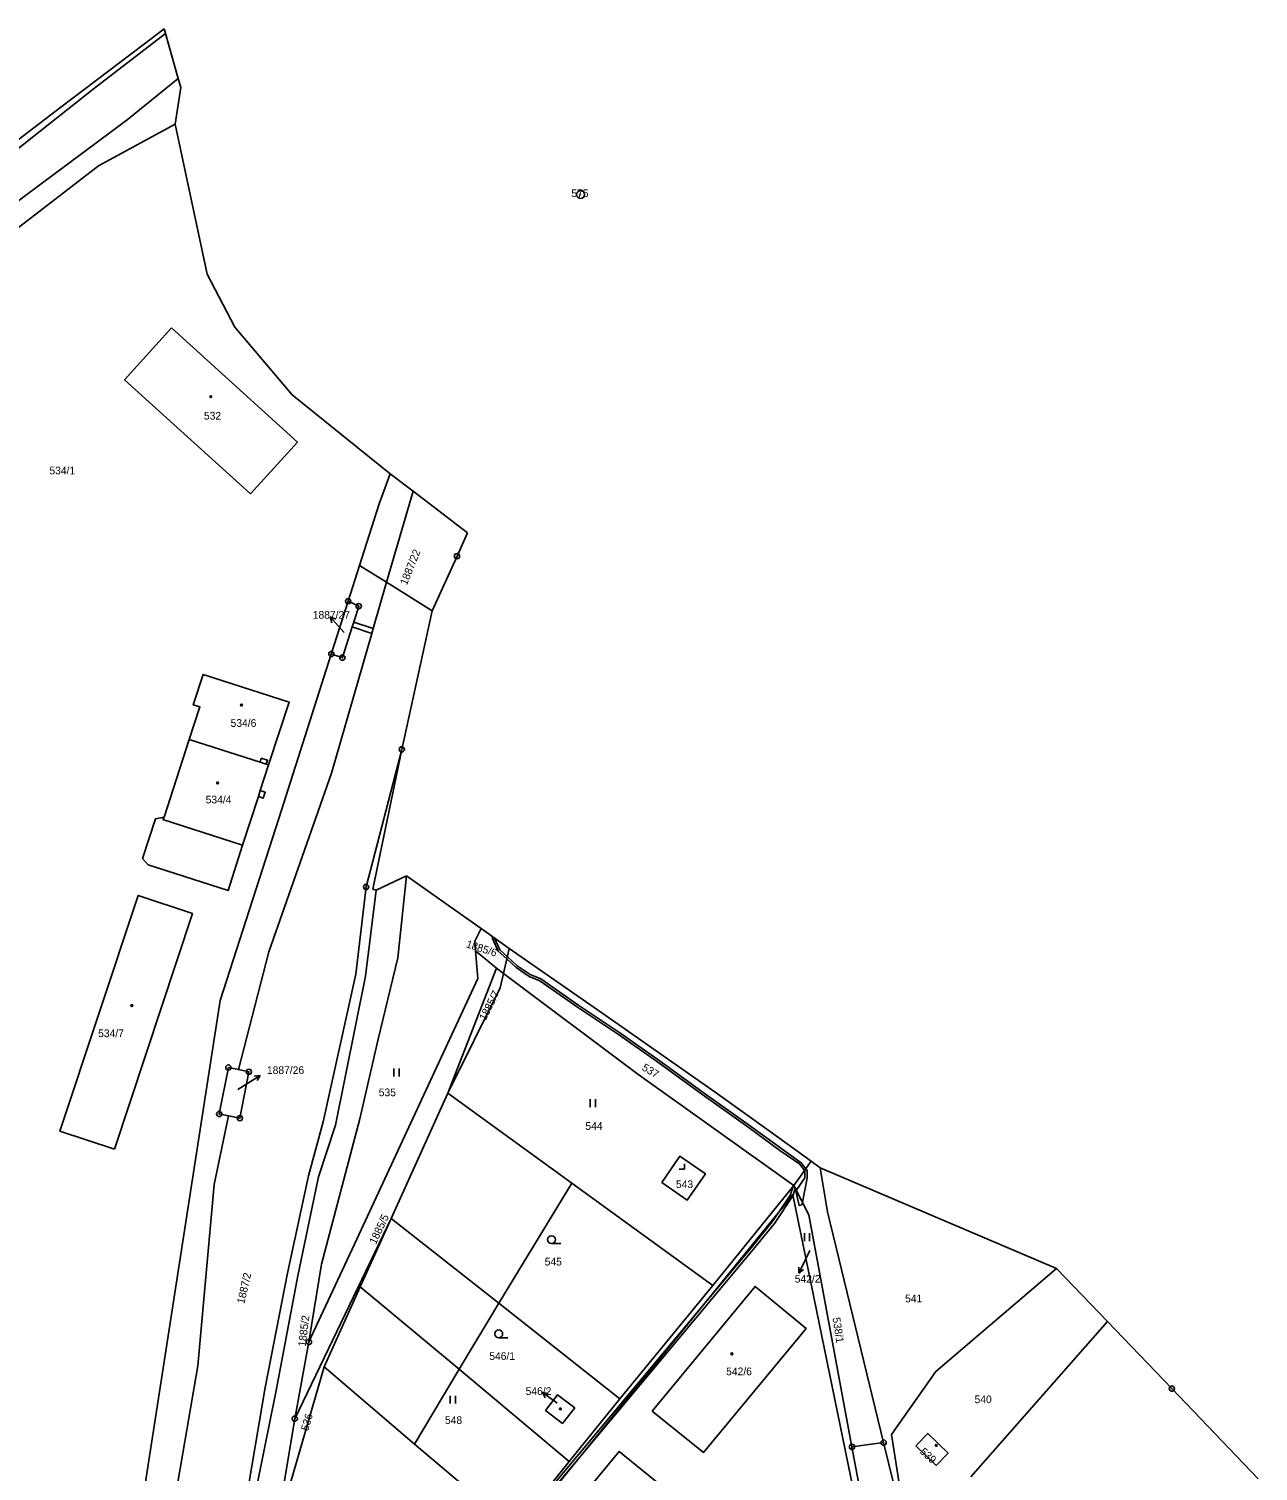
# Model space of a CAD drawing. Extents: x -587171 to -555306, y -1167727 to -1074732.
# Drawn here: x -561111.1 to -560877.8, y -1077658.3 to -1077384.6 of the extents above; entities that cross this region are included whole.
import ezdxf

# ---------------------------------------------------------------- set-up
doc = ezdxf.new("R2010")
doc.units = 0
for name, color, linetype in [('Hranice parcel', 7, 'Continuous'), ('Parcelní čísla', 7, 'Continuous'), ('Pop  PČ popisy', 7, 'Continuous'), ('Vnitřní kresba', 7, 'Continuous'), ('Věcná břemena k části', 7, 'Continuous'), ('Značky bodu BP', 7, 'Continuous'), ('Značky budov', 7, 'Continuous'), ('Značky kultur', 7, 'Continuous')]:
    doc.layers.add(name, color=color, linetype=linetype)

msp = doc.modelspace()

# ---------------------------------------------------------------- linework, layer by layer
at = {"layer": 'Hranice parcel'}
for p, q in [((-561089.39, -1077387.63), (-561085.41, -1077384.6)), ((-561104.98, -1077399.49), (-561089.39, -1077387.63)), ((-561083.3, -1077402.66), (-561082.24, -1077395.75)), ((-561136.14, -1077423.19), (-561104.98, -1077399.49)), ((-561097.85, -1077410.62), (-561083.3, -1077402.66)), ((-561077.2, -1077431.15), (-561083.3, -1077402.66)), ((-561044.6, -1077474.75), (-561042.48, -1077469.05)), ((-561048.31, -1077486.41), (-561044.6, -1077474.75)), ((-561038.17, -1077472.34), (-561027.8, -1077480.27)), ((-561027.8, -1077480.27), (-561029.82, -1077484.67)), ((-561029.82, -1077484.67), (-561034.56, -1077495.01)), ((-561050.47, -1077493.22), (-561048.31, -1077486.41)), ((-561050.47, -1077493.22), (-561053.67, -1077503.25)), ((-561034.56, -1077495.01), (-561040.3, -1077521.34)), ((-561040.3, -1077521.34), (-561047.07, -1077547.44)), ((-561040.3, -1077521.34), (-561045.79, -1077547.85)), ((-561045.15, -1077548.03), (-561039.41, -1077545.32)), ((-561039.41, -1077545.32), (-561041.08, -1077560.86)), ((-561035.74, -1077547.92), (-561039.41, -1077545.32)), ((-561045.15, -1077548.03), (-561047.16, -1077564.4)), ((-561045.79, -1077547.85), (-561045.15, -1077548.03)), ((-561028.18, -1077553.26), (-561035.74, -1077547.92)), ((-561025.24, -1077555.34), (-561028.18, -1077553.26)), ((-561026.45, -1077557.71), (-561025.24, -1077555.34)), ((-561025.24, -1077555.34), (-561019.93, -1077559.09)), ((-561026.3, -1077559.58), (-561026.45, -1077557.71)), ((-561022.35, -1077562.87), (-561026.3, -1077559.58)), ((-561019.93, -1077559.09), (-561021.01, -1077563.88)), ((-561019.93, -1077559.09), (-561002.33, -1077571.3)), ((-561031.57, -1077586.54), (-561022.35, -1077562.87)), ((-561022.35, -1077562.87), (-561021.01, -1077563.88)), ((-561021.01, -1077563.88), (-561021.61, -1077566.57)), ((-561021.01, -1077563.88), (-560995.54, -1077582.99)), ((-561021.61, -1077566.57), (-561031.57, -1077586.54)), ((-561002.33, -1077571.3), (-560980.81, -1077586.39)), ((-560995.54, -1077582.99), (-560965.94, -1077604.07)), ((-561031.57, -1077586.54), (-561042.32, -1077610.36)), ((-560980.81, -1077586.39), (-560971.06, -1077593.43)), ((-560971.06, -1077593.43), (-560962.64, -1077599.49)), ((-560965.94, -1077604.07), (-560962.64, -1077599.49)), ((-560962.64, -1077599.49), (-560960.9, -1077600.75)), ((-560960.9, -1077600.75), (-560916.1, -1077619.85)), ((-560981.28, -1077623.05), (-560965.94, -1077604.07)), ((-561042.32, -1077610.36), (-561060.6, -1077648.34)), ((-561048.19, -1077623.34), (-561042.32, -1077610.36)), ((-560916.1, -1077619.85), (-560906.37, -1077629.88)), ((-561055, -1077638.52), (-561048.19, -1077623.34)), ((-560998.9, -1077644.59), (-560981.28, -1077623.05)), ((-560932.31, -1077659.38), (-560906.37, -1077629.88)), ((-560906.37, -1077629.88), (-560894.18, -1077642.64)), ((-561060.6, -1077648.34), (-561057.92, -1077633.79)), ((-561064.14, -1077669.78), (-561055, -1077638.52)), ((-561066.21, -1077642.45), (-561069.95, -1077664.47)), ((-560894.18, -1077642.64), (-560877.81, -1077659.77)), ((-561008.51, -1077656.44), (-560998.9, -1077644.59)), ((-560954.88, -1077653.68), (-560948.87, -1077652.87)), ((-560954.88, -1077653.68), (-560951.31, -1077672.99)), ((-560944.05, -1077672.73), (-560948.87, -1077652.87)), ((-561018.85, -1077669.25), (-561008.51, -1077656.44))]:
    msp.add_line(p, q, dxfattribs=at)
for points in [[(-561082.24, -1077395.75), (-561082.73, -1077394.02), (-561085.16, -1077385.46), (-561085.41, -1077384.6)], [(-561186.29, -1077567.08), (-561184.34, -1077548.64), (-561179.96, -1077521.59), (-561171.23, -1077492.79), (-561162.55, -1077475.12), (-561152.1, -1077458.73), (-561141.46, -1077444.02), (-561123.47, -1077428.97), (-561118.92, -1077426.82), (-561097.85, -1077410.62)], [(-561042.48, -1077469.05), (-561061.08, -1077454.04), (-561071.96, -1077441.19), (-561077.2, -1077431.15)], [(-561084.02, -1077441.36), (-561060.11, -1077463.02), (-561069, -1077472.82), (-561092.91, -1077451.18), (-561084.02, -1077441.36)], [(-561042.48, -1077469.05), (-561038.9, -1077471.78), (-561038.17, -1077472.34)], [(-561034.56, -1077495.01), (-561043.17, -1077489.63), (-561048.31, -1077486.41)], [(-561053.67, -1077503.25), (-561051.57, -1077503.92), (-561049.72, -1077498.1), (-561049.43, -1077497.19), (-561048.47, -1077494.15), (-561050.47, -1077493.22)], [(-561091.86, -1077681.63), (-561089.7, -1077665.29), (-561074.75, -1077568.98), (-561063.6, -1077534.48), (-561053.67, -1077503.25)], [(-561065.57, -1077524.27), (-561063.56, -1077518.16), (-561061.68, -1077512.35), (-561078, -1077507.1), (-561079.88, -1077512.86), (-561078.6, -1077513.27), (-561080.62, -1077519.46)], [(-561080.62, -1077519.46), (-561085.39, -1077534.21), (-561087.06, -1077534.53), (-561089.47, -1077542.01), (-561088.41, -1077543.24), (-561073.26, -1077548.12), (-561070.5, -1077539.52)], [(-561065.57, -1077524.27), (-561066.01, -1077524.13), (-561065.77, -1077523.41), (-561066.97, -1077523.03), (-561067.2, -1077523.73), (-561080.62, -1077519.46)], [(-561070.5, -1077539.52), (-561067.51, -1077530.27), (-561066.6, -1077530.56), (-561066.25, -1077529.44), (-561067.15, -1077529.15), (-561065.57, -1077524.27)], [(-561047.07, -1077547.44), (-561049.05, -1077564.01), (-561055.23, -1077591.99), (-561058.03, -1077602.23), (-561061.99, -1077620.72), (-561066.21, -1077642.45)], [(-561094.83, -1077597.2), (-561080.04, -1077552.47), (-561090.35, -1077549.03), (-561105.17, -1077593.77), (-561094.83, -1077597.2)], [(-561057.92, -1077633.79), (-561048.86, -1077614.29), (-561025.87, -1077564.82), (-561026.3, -1077559.58)], [(-561041.08, -1077560.86), (-561044.81, -1077576.33), (-561048.24, -1077591.47), (-561055.56, -1077618.99), (-561057.92, -1077633.79)], [(-561047.16, -1077564.4), (-561052.89, -1077592.64), (-561056.11, -1077602.43), (-561060, -1077621.24), (-561064.23, -1077643.29), (-561067.46, -1077659.56), (-561068.21, -1077663.34)], [(-561069.31, -1077582.52), (-561071.29, -1077582.11), (-561073.21, -1077581.71), (-561074.93, -1077590.51), (-561073.21, -1077590.87), (-561071.02, -1077591.32), (-561069.31, -1077582.52)], [(-561031.57, -1077586.54), (-561008.03, -1077603.66), (-560981.28, -1077623.05)], [(-560990.97, -1077603.55), (-560986.18, -1077606.89), (-560982.7, -1077601.89), (-560987.52, -1077598.53), (-560990.97, -1077603.55)], [(-560948.87, -1077652.87), (-560959.51, -1077609.08), (-560960.9, -1077600.75)], [(-560952.12, -1077674.01), (-560966.12, -1077605.89), (-561018.09, -1077669.9)], [(-560965.94, -1077604.07), (-560963.04, -1077609.64), (-560954.88, -1077653.68)], [(-561042.32, -1077610.36), (-561021.9, -1077626.43), (-560998.9, -1077644.59)], [(-560916.1, -1077619.85), (-560938.99, -1077639.39), (-560947.41, -1077651.33), (-560944.05, -1077672.73)], [(-561048.19, -1077623.34), (-561029.43, -1077638.93), (-561008.51, -1077656.44)], [(-560992.78, -1077646.93), (-560973.25, -1077623.25), (-560963.58, -1077631.23), (-560983.08, -1077654.78), (-560992.78, -1077646.93)], [(-561055, -1077638.52), (-561037.9, -1077653.16), (-561018.85, -1077669.25)], [(-561013.05, -1077646.78), (-561010.74, -1077643.79), (-561007.47, -1077646.31), (-561009.82, -1077649.25), (-561013.05, -1077646.78)], [(-561060.6, -1077648.34), (-561062.29, -1077658.56), (-561064.14, -1077669.78)], [(-560942.77, -1077653.5), (-560938.9, -1077657.22), (-560936.64, -1077654.88), (-560940.5, -1077651.13), (-560942.77, -1077653.5)], [(-561014.38, -1077673.09), (-560999.06, -1077654.59), (-560984.66, -1077666.25), (-561000.35, -1077685.17)]]:
    msp.add_lwpolyline(points, dxfattribs=at)
at = {"layer": 'Pop  PČ popisy'}
for p, q in [((-561051.86, -1077498.44), (-561053.87, -1077496.21)), ((-561053.87, -1077496.21), (-561052.83, -1077496.62)), ((-561053.87, -1077496.21), (-561053.57, -1077497.29)), ((-561051.22, -1077499.14), (-561051.86, -1077498.44)), ((-561069.73, -1077584.82), (-561067.19, -1077583.23)), ((-561067.19, -1077583.23), (-561068.3, -1077583.34)), ((-561067.19, -1077583.23), (-561067.77, -1077584.19)), ((-561071.4, -1077585.88), (-561069.73, -1077584.82)), ((-560962.88, -1077616.45), (-560963.64, -1077618.01)), ((-560964.96, -1077620.71), (-560964.97, -1077619.59)), ((-560963.64, -1077618.01), (-560964.96, -1077620.71)), ((-560964.96, -1077620.71), (-560964.07, -1077620.03)), ((-561011.15, -1077645.12), (-561013.61, -1077643.4)), ((-561013.61, -1077643.4), (-561012.5, -1077643.56)), ((-561013.61, -1077643.4), (-561013.08, -1077644.38)), ((-561010.8, -1077645.37), (-561011.15, -1077645.12))]:
    msp.add_line(p, q, dxfattribs=at)
at = {"layer": 'Vnitřní kresba'}
for p, q in [((-561098.89, -1077396.06), (-561085.16, -1077385.46)), ((-561092.38, -1077401.88), (-561082.73, -1077394.02)), ((-561122.69, -1077414.91), (-561098.89, -1077396.06)), ((-561117.31, -1077420.35), (-561092.38, -1077401.88)), ((-561043.17, -1077489.63), (-561038.17, -1077472.34)), ((-561045.7, -1077498.4), (-561043.17, -1077489.63)), ((-561053.63, -1077525.84), (-561045.98, -1077499.36)), ((-561045.98, -1077499.36), (-561049.72, -1077498.1)), ((-561049.43, -1077497.19), (-561045.7, -1077498.4)), ((-561045.98, -1077499.36), (-561045.7, -1077498.4)), ((-561066.01, -1077524.13), (-561067.2, -1077523.73)), ((-561065.55, -1077559.77), (-561053.63, -1077525.84)), ((-561067.51, -1077530.27), (-561067.15, -1077529.15)), ((-561085.39, -1077534.21), (-561085.61, -1077534.64)), ((-561085.61, -1077534.64), (-561070.5, -1077539.52)), ((-561071.29, -1077582.11), (-561065.55, -1077559.77)), ((-561075.89, -1077603.92), (-561073.21, -1077590.87)), ((-561079.03, -1077638.29), (-561075.89, -1077603.92)), ((-561021.9, -1077626.43), (-561008.03, -1077603.66)), ((-561029.43, -1077638.93), (-561021.9, -1077626.43)), ((-561037.9, -1077653.16), (-561029.43, -1077638.93))]:
    msp.add_line(p, q, dxfattribs=at)
msp.add_lwpolyline([(-561092.24, -1077729.79), (-561088.54, -1077699.33), (-561083.87, -1077666.65), (-561079.03, -1077638.29)], dxfattribs=at)
at = {"layer": 'Věcná břemena k části'}
for points in [[(-561022.69, -1077557.14), (-561023.06, -1077556.88), (-561023.11, -1077557.21), (-561022.02, -1077559.6), (-561020.38, -1077561.1), (-561018.62, -1077562.72), (-561016.13, -1077564.41), (-561014.1, -1077565.24), (-561006.93, -1077570.24), (-560999.17, -1077575.46), (-560991.95, -1077580.51), (-560983.36, -1077586.75), (-560974.36, -1077593.15), (-560968.56, -1077597.42), (-560964.78, -1077600.06), (-560963.91, -1077601.25), (-560963.8, -1077601.4), (-560963.81, -1077602.62), (-560965.44, -1077605.03), (-560964.29, -1077607.23), (-560963.41, -1077602.72), (-560963.4, -1077601.26), (-560963.66, -1077600.91), (-560964.5, -1077599.77), (-560974.12, -1077592.83), (-560983.12, -1077586.43), (-560991.71, -1077580.19), (-560998.95, -1077575.13), (-561006.71, -1077569.91), (-561013.9, -1077564.88), (-561015.94, -1077564.05), (-561018.38, -1077562.4), (-561020.28, -1077560.65), (-561021.69, -1077559.36)], [(-560964.29, -1077607.23), (-560965.44, -1077605.03), (-560965.52, -1077605.14), (-560964.89, -1077607.89), (-560964.4, -1077607.78)]]:
    msp.add_lwpolyline(points, close=True, dxfattribs=at)
msp.add_lwpolyline([(-561012.37, -1077662.64), (-561005.97, -1077654.97), (-560973.63, -1077616.21), (-560969.6, -1077611.29), (-560966.09, -1077606.05), (-560965.67, -1077604.65), (-560965.65, -1077604.63), (-560965.88, -1077604.18), (-560966.11, -1077604.35), (-560966.55, -1077605.84), (-560968.77, -1077609.15), (-560970, -1077610.99), (-560974.01, -1077615.89), (-560982.44, -1077625.99), (-561012.75, -1077662.32)], dxfattribs=at)
at = {"layer": 'Značky bodu BP'}
for centre, radius in [((-561006.37, -1077416.03), 0.75), ((-561006.37, -1077416.03), 0.03), ((-561029.82, -1077484.67), 0.5), ((-561029.82, -1077484.67), 0.0303), ((-561050.47, -1077493.22), 0.5), ((-561050.47, -1077493.22), 0.0303), ((-561048.47, -1077494.15), 0.5), ((-561048.47, -1077494.15), 0.0303), ((-561053.67, -1077503.25), 0.5), ((-561053.67, -1077503.25), 0.0303), ((-561051.57, -1077503.92), 0.5), ((-561051.57, -1077503.92), 0.0303), ((-561040.3, -1077521.34), 0.5), ((-561040.3, -1077521.34), 0.0303), ((-561047.07, -1077547.44), 0.5), ((-561047.07, -1077547.44), 0.0303), ((-561073.21, -1077581.71), 0.5), ((-561073.21, -1077581.71), 0.0303), ((-561069.31, -1077582.52), 0.5), ((-561069.31, -1077582.52), 0.0303), ((-561074.93, -1077590.51), 0.5), ((-561074.93, -1077590.51), 0.0303), ((-561071.02, -1077591.32), 0.5), ((-561071.02, -1077591.32), 0.0303), ((-561057.92, -1077633.79), 0.5), ((-561057.92, -1077633.79), 0.0303), ((-560894.18, -1077642.64), 0.5), ((-560894.18, -1077642.64), 0.0303), ((-561060.6, -1077648.34), 0.5), ((-561060.6, -1077648.34), 0.0303), ((-560948.87, -1077652.87), 0.5), ((-560954.88, -1077653.68), 0.5), ((-560954.88, -1077653.68), 0.0303), ((-560948.87, -1077652.87), 0.0303)]:
    msp.add_circle(centre, radius, dxfattribs=at)
at = {"layer": 'Značky budov'}
for centre in [(-561076.53, -1077454.4), (-561070.72, -1077512.92), (-561075.24, -1077527.7), (-561091.51, -1077569.94), (-560977.66, -1077636.03), (-561010.21, -1077646.5), (-560938.88, -1077653.41)]:
    msp.add_circle(centre, 0.175, dxfattribs=at)
at = {"layer": 'Značky kultur'}
for p, q in [((-561041.79, -1077583.42), (-561041.79, -1077581.92)), ((-561040.79, -1077583.42), (-561040.79, -1077581.92)), ((-561004.54, -1077589.24), (-561004.54, -1077587.74)), ((-561003.54, -1077589.24), (-561003.54, -1077587.74)), ((-560986.67, -1077600.99), (-560986.67, -1077599.99)), ((-560987.67, -1077600.99), (-560986.67, -1077600.99)), ((-560963.91, -1077614.64), (-560963.91, -1077613.14)), ((-560962.91, -1077614.64), (-560962.91, -1077613.14)), ((-561011.89, -1077615.12), (-561010.14, -1077615.12)), ((-561021.91, -1077632.99), (-561020.16, -1077632.99)), ((-561031.14, -1077645.48), (-561031.14, -1077643.98)), ((-561030.14, -1077645.48), (-561030.14, -1077643.98))]:
    msp.add_line(p, q, dxfattribs=at)
for centre in [(-561011.89, -1077614.37), (-561021.91, -1077632.24)]:
    msp.add_circle(centre, 0.75, dxfattribs=at)

# ---------------------------------------------------------------- texts
at = {"layer": 'Parcelní čísla'}
for s, p in [('532', (-561077.84, -1077458.75)), ('534/1', (-561107.16, -1077469.14)), ('1887/27', (-561057.19, -1077496.53)), ('534/6', (-561072.78, -1077517.06)), ('534/4', (-561077.51, -1077531.59)), ('534/7', (-561097.92, -1077575.94)), ('1887/26', (-561065.89, -1077582.93)), ('535', (-561044.67, -1077587.15)), ('544', (-561005.46, -1077593.53)), ('543', (-560988.28, -1077604.58)), ('545', (-561013.18, -1077619.27)), ('542/2', (-560965.74, -1077622.52)), ('541', (-560944.81, -1077626.26)), ('546/1', (-561023.7, -1077637.2)), ('542/6', (-560978.75, -1077640.1)), ('546/2', (-561016.8, -1077643.84)), ('540', (-560931.62, -1077645.4)), ('548', (-561032.11, -1077649.35))]:
    msp.add_text(s, height=1.46, dxfattribs=at).set_placement(p)
for s, rotation, p in [('1887/22', 68, (-561039.35, -1077490.28)), ('1885/6', 342, (-561028.21, -1077558.86)), ('1885/7', 63, (-561024.4, -1077572.91)), ('537', 329, (-560994.86, -1077582.1)), ('1885/5', 65, (-561045.22, -1077615.38)), ('1887/2', 77, (-561070.19, -1077626.64)), ('1885/2', 83, (-561058.54, -1077634.73)), ('538/1', 279, (-560958.58, -1077629.23)), ('536', 74, (-561058.06, -1077650.75)), ('539', 318, (-560942.11, -1077654.78))]:
    msp.add_text(s, height=1.46, rotation=rotation, dxfattribs=at).set_placement(p)
at = {"layer": 'Značky bodu BP'}
msp.add_text('575', height=1.46, dxfattribs=at).set_placement((-561008.13, -1077416.53))

doc.saveas('drawing.dxf')
